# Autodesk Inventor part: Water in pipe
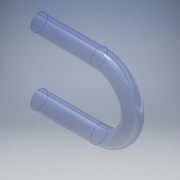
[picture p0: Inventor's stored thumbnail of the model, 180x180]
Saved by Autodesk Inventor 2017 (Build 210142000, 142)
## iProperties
Created: 2020-03
Part Number: Water in pipe
Material: Water
Document SubType Name: Modeling
Designer: user
Density: 0.9983 g/cm^3
Appearance: Tropical Blue
Author: user
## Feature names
1. Sweep1
## Parameters: d1 = 25 mm, d2 = 45 mm, d3 = 45 mm, d4 = 12.5 mm, d5 = 0, d6 = 0
